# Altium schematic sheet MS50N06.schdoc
size 127 x 101 mm
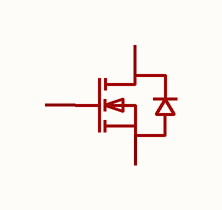
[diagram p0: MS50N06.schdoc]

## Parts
Q?  ms50n06  [TO-252-2_L6.6-W6.1-P4.57-LS10.0-BR-CW]  (value not drawn)

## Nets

Not connected (* = marked no-connect by the designer): Q? 1(G) 2(D) 3(S)

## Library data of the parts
Q? = ms50n06: 数量:1个N沟道;漏源电压(Vdss):60V;连续漏极电流(Id):50A;导通电阻(RDS(on)):12mΩ@10V;耗散功率(Pd):65W;阈值电压(Vgs(th)):1.6V;; Manufacturer: MSKSEMI(美森科); AddInBom: yes; ModelId: 16697a7febd74ea38893a430a7be29f0; ModelTransform: 393.7,259.842,0,0,0,0,-34.45,-0.005,0; Number: 1个N沟道; Drain to Source Voltage: 60V; Current - Continuous Drain(Id): 50A; Pd - Power Dissipation: 65W; Gate Threshold Voltage (Vgs(th)): 1.6V; Gate Charge(Qg): 28nC@10V; Input Capacitance(Ciss): 1.68nF; Reverse Transfer Capacitance (Crss@Vds): 85pF; Type: N沟道; Output Capacitance(Coss): 115pF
